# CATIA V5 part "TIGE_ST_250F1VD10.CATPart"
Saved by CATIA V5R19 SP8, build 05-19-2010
Part number: TIGE_ST_250F1VD10
Nomenclature: 38_b
Source: Unknown
Description: NOT SPECIFIED
Bounding box of the stored display mesh (mm): x -250 to 10, y -5 to 5, z -5 to 5
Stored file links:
  C:\Users\rphgr\Desktop\0_Tapis_TC520B_vitesse\TIGE_ST_250F1VD10.CATPart
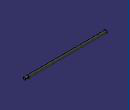
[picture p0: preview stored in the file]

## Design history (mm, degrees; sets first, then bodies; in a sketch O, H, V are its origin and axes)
AxisSystem1: origin (0, 0, 0), X (1, 0, 0), Y (0, 1, 0), Z (0, 0, 1)
Body1 "MANIFOLD_SOLID_BREP #15796" (main body)
  Solid1: solid without history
